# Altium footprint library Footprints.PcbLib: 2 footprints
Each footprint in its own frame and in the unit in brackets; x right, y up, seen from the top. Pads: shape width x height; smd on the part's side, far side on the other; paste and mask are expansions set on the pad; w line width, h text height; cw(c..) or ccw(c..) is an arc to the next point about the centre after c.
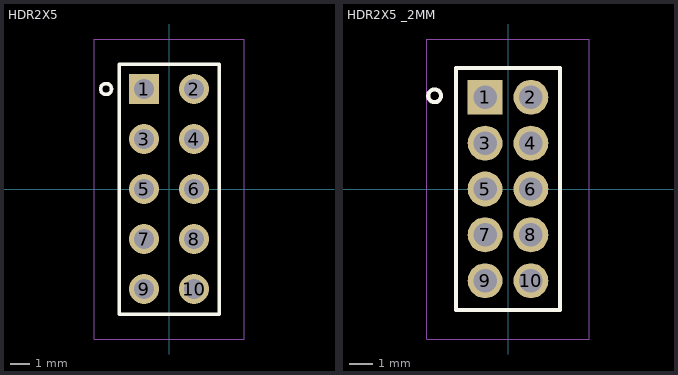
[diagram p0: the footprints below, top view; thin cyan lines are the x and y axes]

## HDR2X5 [mm] "CONN, MALE, 2.54 MM PITCH, 10-PIN"
height 8.38
pads (10):
  rect 1.52x1.52 / inner round 1.52 / far side rect 1.52x1.52 hole 1.02: 1(-1.27,5.08)
  round 1.52 hole 1.02: 2(1.27,5.08) 3(-1.27,2.54) 4(1.27,2.54) 5(-1.27,0) 6(1.27,0) 7(-1.27,-2.54) 8(1.27,-2.54) 9(-1.27,-5.08) 10(1.27,-5.08)
Top Overlay:
  circle w0.178: c-3.2,5.08 r0.279
  lines w0.178: -2.54,-6.35 2.54,-6.35 2.54,6.35 -2.54,6.35 -2.54,-6.35
  text ".Designator" at -1.524,7.493 h1.02
Bottom Overlay:
  lines w0.178: -2.54,-6.319 -2.54,-3.429 ; -2.54,-1.43 -2.54,1.46 ; -2.54,3.57 -2.54,6.35 -0.6,6.35 ; -2.483,-6.35 -0.768,-6.35 ; 0.58,6.35 2.52,6.35 ; 0.825,-6.35 2.54,-6.35 2.54,-3.545 ; 2.54,-1.69 2.54,1.375 ; 2.54,3.31 2.54,6.35
Mechanical 5:
  circle w0.127: c-3.2,5.08 r0.279
  lines w0.127: -2.54,-6.35 -2.54,6.35 2.54,6.35 2.54,-6.35 -2.54,-6.35
  text ".Designator" at -1.524,-0.508 h1.02
Mechanical 15:
  lines w0.05: -3.81,-7.62 -3.81,7.62 3.81,7.62 3.81,-7.62 -3.81,-7.62
3D body: height 8.38, standoff 0, extent -2.54,-6.35 2.54,6.35

## HDR2X5 _2MM [mm] "CONN, MALE, 2 MM PITCH, 10-PIN"
height 8.38
pads (10):
  rect 1.52x1.52 / inner round 1.52 / far side rect 1.52x1.52 hole 1.02: 1(-1,4)
  round 1.52 hole 1.02: 2(1,4) 3(-1,2) 4(1,2) 5(-1,0) 6(1,0) 7(-1,-2) 8(1,-2) 9(-1,-4) 10(1,-4)
Top Overlay:
  circle w0.178: c-3.2,4.064 r0.279
  lines w0.178: -2.27,-5.27 2.27,-5.27 2.27,5.27 -2.27,5.27 -2.27,-5.27
  text ".Designator" at -1.524,6.477 h1.02
Bottom Overlay:
  lines w0.178: -2.27,-2.413 -2.27,-5.27 -0.767,-5.27 ; -2.27,2.427 -2.27,5.207 ; -2.27,5.27 -0.6,5.27 ; 0.58,5.27 2.27,5.27 ; 0.825,-5.27 2.27,-5.27 ; 2.27,-5.207 2.27,-2.402 ; 2.27,2.667 2.27,5.207
Mechanical 5:
  circle w0.127: c-3.2,4.064 r0.279
  lines w0.127: -2.27,-5.27 -2.27,5.27 2.27,5.27 2.27,-5.27 -2.27,-5.27
  text ".Designator" at -1.524,-0.508 h1.02
Mechanical 15:
  lines w0.05: -3.54,-6.54 -3.54,6.54 3.54,6.54 3.54,-6.54 -3.54,-6.54
3D body: height 2, standoff 0, extent -2.27,-5.27 2.27,5.27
